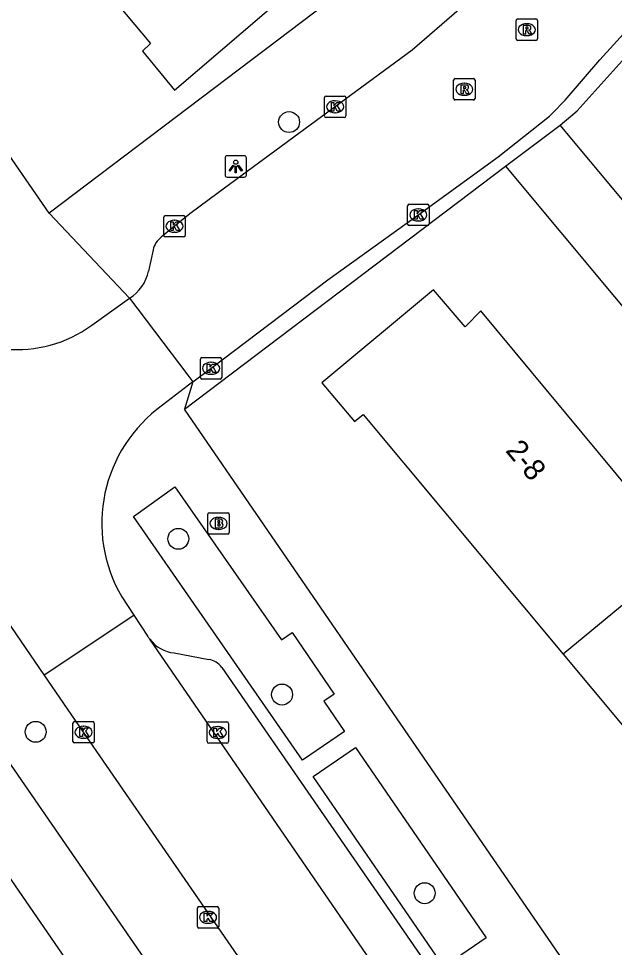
# Model space of a CAD drawing. Extents: x 159888 to 160757, y 384031 to 384746.
# Drawn here: x 160311.17 to 160339.01, y 384241.11 to 384284.54 of the extents above; entities that cross this region are included whole.
import ezdxf

# ---------------------------------------------------------------- set-up
doc = ezdxf.new("R2010")
doc.units = 0
for name, color, linetype in [('IMGEO_Boom', 7, 'Continuous'), ('IMGEO_Brandkraan', 7, 'Continuous'), ('IMGEO_Fietspad_gesloten', 7, 'Continuous'), ('IMGEO_Kolk', 7, 'Continuous'), ('IMGEO_Lichtpunt', 7, 'Continuous'), ('IMGEO_Pand', 7, 'Continuous'), ('IMGEO_Pand_nummerreeks', 7, 'Continuous'), ('IMGEO_Rijbaan_lokaal_open', 7, 'Continuous'), ('IMGEO_Rioolput', 7, 'Continuous'), ('IMGEO_Voetpad_open', 7, 'Continuous')]:
    doc.layers.add(name, color=color, linetype=linetype)

msp = doc.modelspace()

# ---------------------------------------------------------------- linework, layer by layer
at = {"layer": 'IMGEO_Boom'}
for centre in [(160323.808, 384279.7), (160318.631, 384260.216), (160323.479, 384252.933), (160311.964, 384251.19), (160330.145, 384243.645)]:
    msp.add_circle(centre, 0.489, dxfattribs=at)
at = {"layer": 'IMGEO_Brandkraan'}
for p, q in [((160320.086, 384261.436), (160320.938, 384261.436)), ((160320.011, 384260.51), (160320.011, 384261.362)), ((160320.499, 384261.216), (160320.524, 384261.216)), ((160321.012, 384261.362), (160321.012, 384260.51)), ((160320.522, 384260.656), (160320.497, 384260.656)), ((160320.938, 384260.436), (160320.086, 384260.436))]:
    msp.add_line(p, q, dxfattribs=at)
for points in [[(160320.086, 384261.436), (160320.938, 384261.436)], [(160320.011, 384260.51), (160320.011, 384261.362)], [(160320.359, 384261.136), (160320.359, 384260.736), (160320.572, 384260.736)], [(160320.59, 384261.136), (160320.359, 384261.136)], [(160320.538, 384261.055), (160320.484, 384261.055), (160320.484, 384260.979)], [(160321.012, 384261.362), (160321.012, 384260.51)], [(160320.484, 384260.979), (160320.537, 384260.979)], [(160320.546, 384260.903), (160320.484, 384260.903), (160320.484, 384260.822)], [(160320.484, 384260.822), (160320.546, 384260.822)], [(160320.938, 384260.436), (160320.086, 384260.436)]]:
    msp.add_lwpolyline(points, dxfattribs=at)
for centre, radius, start, end in [((160320.088, 384261.36), 0.0765, 91.552, 178.448), ((160320.088, 384261.36), 0.0765, 91.552, 178.448), ((160320.936, 384261.36), 0.0765, 1.552, 88.448), ((160320.936, 384261.36), 0.0765, 1.552, 88.448), ((160320.539, 384261.017), 0.0379, 267.8285, 90.9355), ((160320.594, 384260.991), 0.145, 59.4692, 91.5367), ((160320.619, 384261.038), 0.0922, 285.5137, 58.1501), ((160320.547, 384260.862), 0.0404, 269.8759, 90.5077), ((160320.578, 384260.987), 0.251, 268.6676, 293.5347), ((160320.624, 384260.846), 0.105, 301.3115, 78.989), ((160320.088, 384260.512), 0.0765, 181.552, 268.448), ((160320.088, 384260.512), 0.0765, 181.552, 268.448), ((160320.936, 384260.512), 0.0765, 271.552, 358.448), ((160320.936, 384260.512), 0.0765, 271.552, 358.448)]:
    msp.add_arc(centre, radius, start, end, dxfattribs=at)
for centre, major_axis, ratio, start_param, end_param in [((160320.498, 384260.936), (-0.387, 0.002), 0.722429, 4.712389, 7.853982), ((160320.523, 384260.936), (-0.39, 0.002), 0.717154, 1.570796, 4.712389)]:
    msp.add_ellipse(centre, major_axis=major_axis, ratio=ratio, start_param=start_param, end_param=end_param, dxfattribs=at)
at = {"layer": 'IMGEO_Fietspad_gesloten'}
for points in [[(160330.691, 384220.794), (160330.585, 384220.947), (160304.748, 384258.435)], [(160301.925, 384257.178), (160328.105, 384219.124)]]:
    msp.add_lwpolyline(points, dxfattribs=at)
at = {"layer": 'IMGEO_Kolk'}
for p, q in [((160325.463, 384279.989), (160325.463, 384280.841)), ((160325.538, 384280.915), (160326.39, 384280.915)), ((160325.951, 384280.695), (160325.976, 384280.695)), ((160326.464, 384280.841), (160326.464, 384279.989)), ((160325.974, 384280.135), (160325.949, 384280.135)), ((160326.39, 384279.915), (160325.538, 384279.915)), ((160329.349, 384274.933), (160329.349, 384275.785)), ((160329.424, 384275.859), (160330.276, 384275.859)), ((160330.35, 384275.785), (160330.35, 384274.933)), ((160329.837, 384275.639), (160329.862, 384275.639)), ((160317.953, 384274.403), (160317.953, 384275.255)), ((160318.028, 384275.329), (160318.88, 384275.329)), ((160318.441, 384275.109), (160318.466, 384275.109)), ((160318.954, 384275.255), (160318.954, 384274.403)), ((160329.86, 384275.079), (160329.835, 384275.079)), ((160318.464, 384274.549), (160318.439, 384274.549)), ((160330.276, 384274.859), (160329.424, 384274.859)), ((160318.88, 384274.329), (160318.028, 384274.329)), ((160319.662, 384267.761), (160319.662, 384268.613)), ((160319.737, 384268.687), (160320.589, 384268.687)), ((160320.15, 384268.467), (160320.175, 384268.467)), ((160320.663, 384268.613), (160320.663, 384267.761)), ((160320.589, 384267.687), (160319.737, 384267.687)), ((160320.173, 384267.907), (160320.148, 384267.907)), ((160313.702, 384250.745), (160313.702, 384251.597)), ((160313.777, 384251.671), (160314.629, 384251.671)), ((160314.19, 384251.451), (160314.215, 384251.451)), ((160314.703, 384251.597), (160314.703, 384250.745)), ((160319.977, 384250.733), (160319.977, 384251.585)), ((160320.052, 384251.659), (160320.904, 384251.659)), ((160320.978, 384251.585), (160320.978, 384250.733)), ((160320.465, 384251.439), (160320.49, 384251.439)), ((160314.629, 384250.671), (160313.777, 384250.671)), ((160314.213, 384250.891), (160314.188, 384250.891)), ((160320.904, 384250.659), (160320.052, 384250.659)), ((160320.488, 384250.879), (160320.463, 384250.879)), ((160319.521, 384242.092), (160319.521, 384242.944)), ((160319.596, 384243.018), (160320.448, 384243.018)), ((160320.009, 384242.798), (160320.034, 384242.798)), ((160320.522, 384242.944), (160320.522, 384242.092)), ((160320.448, 384242.018), (160319.596, 384242.018)), ((160320.032, 384242.238), (160320.007, 384242.238))]:
    msp.add_line(p, q, dxfattribs=at)
for points in [[(160325.463, 384279.989), (160325.463, 384280.841)], [(160325.538, 384280.915), (160326.39, 384280.915)], [(160325.784, 384280.615), (160325.907, 384280.615), (160325.907, 384280.464), (160326.037, 384280.615), (160326.201, 384280.615), (160326.055, 384280.464), (160326.208, 384280.215), (160326.056, 384280.215), (160325.971, 384280.379), (160325.907, 384280.312), (160325.907, 384280.215), (160325.784, 384280.215), (160325.784, 384280.615)], [(160326.464, 384280.841), (160326.464, 384279.989)], [(160326.39, 384279.915), (160325.538, 384279.915)], [(160329.349, 384274.933), (160329.349, 384275.785)], [(160329.424, 384275.859), (160330.276, 384275.859)], [(160330.35, 384275.785), (160330.35, 384274.933)], [(160329.67, 384275.559), (160329.793, 384275.559), (160329.793, 384275.408), (160329.923, 384275.559), (160330.087, 384275.559), (160329.941, 384275.408), (160330.094, 384275.159), (160329.942, 384275.159), (160329.857, 384275.323), (160329.793, 384275.256), (160329.793, 384275.159), (160329.67, 384275.159), (160329.67, 384275.559)], [(160317.953, 384274.403), (160317.953, 384275.255)], [(160318.028, 384275.329), (160318.88, 384275.329)], [(160318.274, 384275.029), (160318.397, 384275.029), (160318.397, 384274.878), (160318.527, 384275.029), (160318.691, 384275.029), (160318.545, 384274.878), (160318.698, 384274.629), (160318.546, 384274.629), (160318.461, 384274.793), (160318.397, 384274.726), (160318.397, 384274.629), (160318.274, 384274.629), (160318.274, 384275.029)], [(160318.954, 384275.255), (160318.954, 384274.403)], [(160330.276, 384274.859), (160329.424, 384274.859)], [(160318.88, 384274.329), (160318.028, 384274.329)], [(160319.662, 384267.761), (160319.662, 384268.613)], [(160319.737, 384268.687), (160320.589, 384268.687)], [(160319.983, 384268.387), (160320.106, 384268.387), (160320.106, 384268.236), (160320.236, 384268.387), (160320.4, 384268.387), (160320.254, 384268.236), (160320.407, 384267.987), (160320.255, 384267.987), (160320.17, 384268.151), (160320.106, 384268.084), (160320.106, 384267.987), (160319.983, 384267.987), (160319.983, 384268.387)], [(160320.663, 384268.613), (160320.663, 384267.761)], [(160320.589, 384267.687), (160319.737, 384267.687)], [(160313.702, 384250.745), (160313.702, 384251.597)], [(160313.777, 384251.671), (160314.629, 384251.671)], [(160314.703, 384251.597), (160314.703, 384250.745)], [(160319.977, 384250.733), (160319.977, 384251.585)], [(160320.052, 384251.659), (160320.904, 384251.659)], [(160320.978, 384251.585), (160320.978, 384250.733)], [(160314.023, 384251.371), (160314.146, 384251.371), (160314.146, 384251.22), (160314.276, 384251.371), (160314.44, 384251.371), (160314.294, 384251.22), (160314.447, 384250.971), (160314.295, 384250.971), (160314.21, 384251.135), (160314.146, 384251.068), (160314.146, 384250.971), (160314.023, 384250.971), (160314.023, 384251.371)], [(160320.298, 384251.359), (160320.421, 384251.359), (160320.421, 384251.208), (160320.551, 384251.359), (160320.715, 384251.359), (160320.569, 384251.208), (160320.722, 384250.959), (160320.57, 384250.959), (160320.485, 384251.123), (160320.421, 384251.056), (160320.421, 384250.959), (160320.298, 384250.959), (160320.298, 384251.359)], [(160314.629, 384250.671), (160313.777, 384250.671)], [(160320.904, 384250.659), (160320.052, 384250.659)], [(160319.521, 384242.092), (160319.521, 384242.944)], [(160319.596, 384243.018), (160320.448, 384243.018)], [(160320.522, 384242.944), (160320.522, 384242.092)], [(160319.842, 384242.718), (160319.965, 384242.718), (160319.965, 384242.567), (160320.095, 384242.718), (160320.259, 384242.718), (160320.113, 384242.567), (160320.266, 384242.318), (160320.114, 384242.318), (160320.029, 384242.482), (160319.965, 384242.415), (160319.965, 384242.318), (160319.842, 384242.318), (160319.842, 384242.718)], [(160320.448, 384242.018), (160319.596, 384242.018)]]:
    msp.add_lwpolyline(points, dxfattribs=at)
for centre, start, end in [((160325.54, 384280.839), 91.552, 178.448), ((160325.54, 384280.839), 91.552, 178.448), ((160326.388, 384280.839), 1.552, 88.448), ((160326.388, 384280.839), 1.552, 88.448), ((160325.54, 384279.991), 181.552, 268.448), ((160325.54, 384279.991), 181.552, 268.448), ((160326.388, 384279.991), 271.552, 358.448), ((160326.388, 384279.991), 271.552, 358.448), ((160329.426, 384275.783), 91.552, 178.448), ((160329.426, 384275.783), 91.552, 178.448), ((160330.274, 384275.783), 1.552, 88.448), ((160330.274, 384275.783), 1.552, 88.448), ((160318.03, 384275.253), 91.552, 178.448), ((160318.03, 384275.253), 91.552, 178.448), ((160318.878, 384275.253), 1.552, 88.448), ((160318.878, 384275.253), 1.552, 88.448), ((160329.426, 384274.935), 181.552, 268.448), ((160329.426, 384274.935), 181.552, 268.448), ((160330.274, 384274.935), 271.552, 358.448), ((160330.274, 384274.935), 271.552, 358.448), ((160318.03, 384274.405), 181.552, 268.448), ((160318.03, 384274.405), 181.552, 268.448), ((160318.878, 384274.405), 271.552, 358.448), ((160318.878, 384274.405), 271.552, 358.448), ((160319.739, 384268.611), 91.552, 178.448), ((160319.739, 384268.611), 91.552, 178.448), ((160320.587, 384268.611), 1.552, 88.448), ((160320.587, 384268.611), 1.552, 88.448), ((160319.739, 384267.763), 181.552, 268.448), ((160319.739, 384267.763), 181.552, 268.448), ((160320.587, 384267.763), 271.552, 358.448), ((160320.587, 384267.763), 271.552, 358.448), ((160313.779, 384251.595), 91.552, 178.448), ((160313.779, 384251.595), 91.552, 178.448), ((160314.627, 384251.595), 1.552, 88.448), ((160314.627, 384251.595), 1.552, 88.448), ((160320.054, 384251.583), 91.552, 178.448), ((160320.054, 384251.583), 91.552, 178.448), ((160320.902, 384251.583), 1.552, 88.448), ((160320.902, 384251.583), 1.552, 88.448), ((160313.779, 384250.747), 181.552, 268.448), ((160313.779, 384250.747), 181.552, 268.448), ((160314.627, 384250.747), 271.552, 358.448), ((160314.627, 384250.747), 271.552, 358.448), ((160320.054, 384250.735), 181.552, 268.448), ((160320.054, 384250.735), 181.552, 268.448), ((160320.902, 384250.735), 271.552, 358.448), ((160320.902, 384250.735), 271.552, 358.448), ((160319.598, 384242.942), 91.552, 178.448), ((160319.598, 384242.942), 91.552, 178.448), ((160320.446, 384242.942), 1.552, 88.448), ((160320.446, 384242.942), 1.552, 88.448), ((160319.598, 384242.094), 181.552, 268.448), ((160319.598, 384242.094), 181.552, 268.448), ((160320.446, 384242.094), 271.552, 358.448), ((160320.446, 384242.094), 271.552, 358.448)]:
    msp.add_arc(centre, 0.0765, start, end, dxfattribs=at)
for centre, major_axis, ratio, start_param, end_param in [((160325.95, 384280.415), (-0.387, 0.002), 0.722429, 4.712389, 7.853982), ((160325.975, 384280.415), (-0.39, 0.002), 0.717154, 1.570796, 4.712389), ((160329.836, 384275.359), (-0.387, 0.002), 0.722429, 4.712389, 7.853982), ((160329.861, 384275.359), (-0.39, 0.002), 0.717154, 1.570796, 4.712389), ((160318.44, 384274.829), (-0.387, 0.002), 0.722429, 4.712389, 7.853982), ((160318.465, 384274.829), (-0.39, 0.002), 0.717154, 1.570796, 4.712389), ((160320.149, 384268.187), (-0.387, 0.002), 0.722429, 4.712389, 7.853982), ((160320.174, 384268.187), (-0.39, 0.002), 0.717154, 1.570796, 4.712389), ((160314.189, 384251.171), (-0.387, 0.002), 0.722429, 4.712389, 7.853982), ((160314.214, 384251.171), (-0.39, 0.002), 0.717154, 1.570796, 4.712389), ((160320.464, 384251.159), (-0.387, 0.002), 0.722429, 4.712389, 7.853982), ((160320.489, 384251.159), (-0.39, 0.002), 0.717154, 1.570796, 4.712389), ((160320.008, 384242.518), (-0.387, 0.002), 0.722429, 4.712389, 7.853982), ((160320.033, 384242.518), (-0.39, 0.002), 0.717154, 1.570796, 4.712389)]:
    msp.add_ellipse(centre, major_axis=major_axis, ratio=ratio, start_param=start_param, end_param=end_param, dxfattribs=at)
at = {"layer": 'IMGEO_Lichtpunt'}
for p, q in [((160320.816, 384278.027), (160320.816, 384277.22)), ((160320.816, 384278.027), (160320.816, 384277.22)), ((160321.718, 384278.122), (160320.91, 384278.122)), ((160321.718, 384278.122), (160320.91, 384278.122)), ((160321.812, 384277.22), (160321.812, 384278.027)), ((160321.812, 384277.22), (160321.812, 384278.027)), ((160320.91, 384277.126), (160321.718, 384277.126)), ((160320.91, 384277.126), (160321.718, 384277.126))]:
    msp.add_line(p, q, dxfattribs=at)
for points in [[(160321.19, 384277.691), (160321.229, 384277.663), (160321.041, 384277.401), (160321.003, 384277.428), (160321.19, 384277.691)], [(160321.292, 384277.643), (160321.339, 384277.643), (160321.339, 384277.321), (160321.292, 384277.321), (160321.292, 384277.643)], [(160321.402, 384277.663), (160321.44, 384277.69), (160321.627, 384277.428), (160321.588, 384277.4), (160321.402, 384277.663)]]:
    msp.add_lwpolyline(points, dxfattribs=at)
msp.add_circle((160321.315, 384277.825), 0.0994, dxfattribs=at)
for centre, start, end in [((160320.91, 384278.027), 90, 180), ((160320.91, 384278.027), 90, 180), ((160321.718, 384278.027), 0, 90), ((160321.718, 384278.027), 0, 90), ((160320.91, 384277.22), 180, 270), ((160320.91, 384277.22), 180, 270), ((160321.718, 384277.22), 270, 0), ((160321.718, 384277.22), 270, 360)]:
    msp.add_arc(centre, 0.0946, start, end, dxfattribs=at)
at = {"layer": 'IMGEO_Pand'}
for points in [[(160307.893, 384294.625), (160317.336, 384283.371), (160316.955, 384283.012), (160318.45, 384281.198), (160323.712, 384285.715), (160322.297, 384287.419), (160323.057, 384287.98), (160313.525, 384299.35)], [(160342.239, 384259.468), (160332.771, 384270.87), (160332.038, 384270.121), (160330.555, 384271.85), (160325.333, 384267.508), (160326.868, 384265.704), (160327.269, 384266.034), (160336.616, 384254.819)], [(160342.239, 384259.468), (160336.616, 384254.819)], [(160336.616, 384254.819), (160340.632, 384250), (160346.039, 384243.463), (160345.684, 384243.17), (160347.147, 384241.401), (160354.506, 384247.489), (160353.105, 384249.183), (160351.726, 384248.043), (160350.101, 384250), (160342.239, 384259.468)]]:
    msp.add_lwpolyline(points, dxfattribs=at)
at = {"layer": 'IMGEO_Rijbaan_lokaal_open'}
for points in [[(160319.303, 384267.551), (160320.163, 384268.187), (160325.613, 384272.322), (160329.833, 384275.348), (160333.576, 384278.079), (160335.984, 384279.983), (160336.104, 384280.105), (160336.716, 384280.731), (160338.331, 384282.617), (160345.01, 384289.972), (160361.399, 384308.557), (160367.398, 384315.345), (160372.06, 384320.608), (160386.091, 384336.349), (160387.995, 384338.559)], [(160331.755, 384284.956), (160329.563, 384283.059), (160327.209, 384281.326), (160320.493, 384276.397), (160319.163, 384275.415), (160318.454, 384274.829), (160317.834, 384274.312)], [(160317.456, 384273.731), (160317.24, 384272.73)], [(160314.59, 384270.204), (160316.352, 384271.463)], [(160316.352, 384271.463), (160319.071, 384267.868), (160319.303, 384267.551)], [(160319.303, 384267.551), (160317.894, 384266.457)], [(160312.362, 384253.857), (160307.611, 384260.791)], [(160315.991, 384257.496), (160316.546, 384256.653)], [(160312.362, 384253.857), (160316.546, 384256.653)], [(160316.546, 384256.653), (160317.21, 384255.643)], [(160333.27, 384232.249), (160330.545, 384236.25), (160317.293, 384255.522)], [(160333.002, 384223.856), (160326.378, 384233.514), (160322.484, 384239.165), (160314.203, 384251.171), (160312.362, 384253.857)]]:
    msp.add_lwpolyline(points, dxfattribs=at)
for centre, radius, start, end in [((160318.355, 384273.56), 0.915, 124.6931, 169.2106), ((160315.282, 384273.157), 2.004, 302.2625, 347.6867), ((160311.106, 384274.957), 5.893, 223.2333, 306.2476), ((160321.843, 384260.936), 6.788, 125.5762, 210.4448), ((160319.011, 384256.789), 2.135, 212.4788, 216.4176)]:
    msp.add_arc(centre, radius, start, end, dxfattribs=at)
at = {"layer": 'IMGEO_Rioolput'}
for p, q in [((160334.492, 384284.52), (160335.344, 384284.52)), ((160334.417, 384283.594), (160334.417, 384284.446)), ((160334.905, 384284.3), (160334.93, 384284.3)), ((160335.418, 384284.446), (160335.418, 384283.594)), ((160334.928, 384283.74), (160334.903, 384283.74)), ((160335.344, 384283.52), (160334.492, 384283.52)), ((160331.499, 384280.806), (160331.499, 384281.658)), ((160331.574, 384281.732), (160332.426, 384281.732)), ((160331.987, 384281.512), (160332.012, 384281.512)), ((160332.5, 384281.658), (160332.5, 384280.806)), ((160332.426, 384280.732), (160331.574, 384280.732)), ((160332.01, 384280.952), (160331.985, 384280.952))]:
    msp.add_line(p, q, dxfattribs=at)
for points in [[(160334.492, 384284.52), (160335.344, 384284.52)], [(160334.417, 384283.594), (160334.417, 384284.446)], [(160335.006, 384284.218), (160334.754, 384284.22), (160334.754, 384283.82)], [(160334.932, 384284.139), (160334.878, 384284.139), (160334.878, 384284.058)], [(160334.878, 384284.058), (160334.93, 384284.058)], [(160335.418, 384284.446), (160335.418, 384283.594)], [(160334.754, 384283.82), (160334.878, 384283.82), (160334.878, 384283.982), (160334.889, 384283.982)], [(160334.936, 384283.953), (160335.007, 384283.82), (160335.147, 384283.82), (160335.082, 384283.946)], [(160335.344, 384283.52), (160334.492, 384283.52)], [(160331.499, 384280.806), (160331.499, 384281.658)], [(160331.574, 384281.732), (160332.426, 384281.732)], [(160332.088, 384281.43), (160331.836, 384281.432), (160331.836, 384281.032)], [(160332.5, 384281.658), (160332.5, 384280.806)], [(160331.836, 384281.032), (160331.96, 384281.032), (160331.96, 384281.194), (160331.971, 384281.194)], [(160332.014, 384281.351), (160331.96, 384281.351), (160331.96, 384281.27)], [(160331.96, 384281.27), (160332.012, 384281.27)], [(160332.018, 384281.165), (160332.089, 384281.032), (160332.229, 384281.032), (160332.164, 384281.158)], [(160332.426, 384280.732), (160331.574, 384280.732)]]:
    msp.add_lwpolyline(points, dxfattribs=at)
for centre, radius, start, end in [((160334.494, 384284.444), 0.0765, 91.552, 178.448), ((160334.494, 384284.444), 0.0765, 91.552, 178.448), ((160335.342, 384284.444), 0.0765, 1.552, 88.448), ((160335.342, 384284.444), 0.0765, 1.552, 88.448), ((160334.914, 384284.247), 0.19, 274.7715, 282.9687), ((160334.938, 384284.043), 0.0964, 77.0061, 93.1865), ((160334.952, 384284.1), 0.0378, 276.6634, 79.6772), ((160335.005, 384284.108), 0.109, 350.3612, 89.416), ((160335.003, 384284.108), 0.112, 277.5842, 350.9817), ((160334.494, 384283.596), 0.0765, 181.552, 268.448), ((160334.494, 384283.596), 0.0765, 181.552, 268.448), ((160334.888, 384283.929), 0.0533, 26.0293, 88.6989), ((160334.987, 384283.893), 0.108, 29.5134, 73.7905), ((160335.342, 384283.596), 0.0765, 271.552, 358.448), ((160335.342, 384283.596), 0.0765, 271.552, 358.448), ((160331.576, 384281.656), 0.0765, 91.552, 178.448), ((160331.576, 384281.656), 0.0765, 91.552, 178.448), ((160332.087, 384281.32), 0.109, 350.3612, 89.416), ((160332.424, 384281.656), 0.0765, 1.552, 88.448), ((160332.424, 384281.656), 0.0765, 1.552, 88.448), ((160331.97, 384281.141), 0.0533, 26.0293, 88.6989), ((160331.996, 384281.459), 0.19, 274.7715, 282.9687), ((160332.02, 384281.255), 0.0964, 77.0061, 93.1865), ((160332.034, 384281.312), 0.0378, 276.6634, 79.6772), ((160332.085, 384281.32), 0.112, 277.5842, 350.9817), ((160332.069, 384281.105), 0.108, 29.5134, 73.7905), ((160331.576, 384280.808), 0.0765, 181.552, 268.448), ((160331.576, 384280.808), 0.0765, 181.552, 268.448), ((160332.424, 384280.808), 0.0765, 271.552, 358.448), ((160332.424, 384280.808), 0.0765, 271.552, 358.448)]:
    msp.add_arc(centre, radius, start, end, dxfattribs=at)
for centre, major_axis, ratio, start_param, end_param in [((160334.904, 384284.02), (-0.387, 0.002), 0.722429, 4.712389, 7.853982), ((160334.929, 384284.02), (-0.39, 0.002), 0.717154, 1.570796, 4.712389), ((160331.986, 384281.232), (-0.387, 0.002), 0.722429, 4.712389, 7.853982), ((160332.011, 384281.232), (-0.39, 0.002), 0.717154, 1.570796, 4.712389)]:
    msp.add_ellipse(centre, major_axis=major_axis, ratio=ratio, start_param=start_param, end_param=end_param, dxfattribs=at)
at = {"layer": 'IMGEO_Voetpad_open'}
for points in [[(160312.595, 384275.443), (160296.596, 384298.647), (160291.109, 384306.696)], [(160329.749, 384288.44), (160312.595, 384275.443)], [(160336.483, 384279.562), (160337.275, 384280.219), (160341.199, 384284.583)], [(160333.927, 384277.642), (160336.483, 384279.562)], [(160360.504, 384250.764), (160336.483, 384279.562)], [(160318.92, 384266.275), (160333.927, 384277.642)], [(160333.927, 384277.642), (160356.959, 384250), (160358.209, 384248.5)], [(160316.352, 384271.463), (160312.595, 384275.443)], [(160319.303, 384267.551), (160318.92, 384266.275)], [(160340.225, 384235.253), (160330.097, 384250), (160318.92, 384266.275)], [(160323.946, 384255.836), (160325.918, 384252.958), (160325.436, 384252.629), (160326.392, 384251.208), (160324.429, 384249.862), (160316.536, 384261.258), (160318.471, 384262.644), (160323.448, 384255.49), (160323.946, 384255.836)], [(160318.435, 384254.878), (160320.056, 384254.577)], [(160320.66, 384254.201), (160332.238, 384237.414), (160333.192, 384236.005)], [(160326.906, 384250.459), (160333.017, 384241.563), (160331.048, 384240.211), (160324.932, 384249.106), (160326.906, 384250.459)]]:
    msp.add_lwpolyline(points, dxfattribs=at)
for centre, radius, start, end in [((160318.607, 384256.518), 1.648, 217.1486, 264.0121), ((160319.87, 384253.605), 0.99, 37.035, 79.1591)]:
    msp.add_arc(centre, radius, start, end, dxfattribs=at)

# ---------------------------------------------------------------- texts
at = {"layer": 'IMGEO_Pand_nummerreeks'}
msp.add_text('2-8', height=1, rotation=309.9364, dxfattribs=at).set_placement((160333.888, 384264.325))

doc.saveas('drawing.dxf')
